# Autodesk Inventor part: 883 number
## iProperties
Author: Vincent Molino
Shininess: 41.0
Angle Display Precision: 2
Document Length Units: 11272
Document Angle Units: 11286
Document Time Units: 11279
Document Mass Units: 11290
Document Length Units Precision: 3
Document Angle Units Precision: 2
Compacted: True
PropertySet Name: _Private Model Information
Created: 2002-05
Part Number: 883 number
Document SubType Name: Modeling
Designer: Vincent Molino
Control State: 0
Master: False
Checked Out: False
PropertySet Name: Design Tracking Control
Density: 0.0
Volumn: 0.0
Area: 0.0
PropertySet Name: Model Information
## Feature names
1. Extrusion1
